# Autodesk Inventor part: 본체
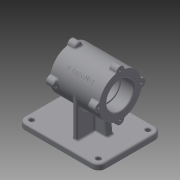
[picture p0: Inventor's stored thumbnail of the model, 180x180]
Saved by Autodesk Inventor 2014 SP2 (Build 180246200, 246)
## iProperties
Created: 2015-12
Part Number: 본체
Material: Generic
Document SubType Name: Modeling
Designer: Administrator
Density: 1 g/cm^3
Appearance: Default
Author: Administrator
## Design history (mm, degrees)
sketch "스케치1"
  geometry: L1 (-70, 55)-(70, 55); L2 (70, 55)-(70, -55); L3 (70, -55)-(-70, -55); L4 (-70, -55)-(-70, 55); 3 further points
  constraints: 8 end point, 2 midpoint, 2 parallel, 1 horizontal, 1 horizontal alignment, 1 perpendicular, 1 vertical alignment
  dimensions: "d0" = 140 distance of L1.start L1.end; "d1" = 110 distance of L3.end L1.start
extrude "돌출1" new body sketch "스케치1" distance "d2" = 10; taper "d3" = 0 deg
node "작업 평면2"
  node "작업 평면1"
sketch "스케치2"
  geometry: L1 (70, -9.931)-(70, -82.976); L2 (-10, -55)-(85.359, -55); C1 r 37 at (70, -55)
  constraints: 4 end point, 2 point on line, 1 centre point, 1 perpendicular, 1 vertical
  dimensions: "d5" = 80 distance from line of L2.start L1; "d6" = 74 diameter of C1
extrude "돌출2" join sketch "스케치2" stored distance "d7" = 85; taper "d8" = 0 deg
sketch "스케치3"
  geometry: L1 (70, -55)-(-10, -55); L2 (0, -110)-(0, 0) reference; L3 (70, -92)-(-6.296, -92); L4 (70, -18)-(-6.296, -18); L5 (70, -18)-(70, -92); L6 (-6.296, -92)-(-6.296, -18); A1 r 37 centre (70, -55) between (70, -92) and (70, -18) reference
  constraints: 10 end point, 2 perpendicular, 2 point on circle, 2 symmetric about line, 1 horizontal, 1 parallel, 1 point on line
  dimensions: "d10" = 37 distance between parallel lines of L1 L3
extrude "돌출3" join sketch "스케치3" stored distance "d11" = 8; taper "d12" = 0 deg
sketch "스케치4"
  geometry: L1 (35, 50.324)-(35, 4.64); L2 (6, 10)-(14, 10) reference; L3 (10, 10)-(10, 60.476); L4 (70, 10)-(-70, 10) reference; L5 (35, 10)-(30.049, 50.324); L6 (35, 10)-(75.627, 10); L7 (-15, 10)-(-10.049, 50.324); L8 (-10.049, 50.324)-(30.049, 50.324); L9 (35, 10)-(-15, 10); 1 further point
  constraints: 14 end point, 2 parallel, 2 point on line, 2 symmetric about line, 1 equal length, 1 horizontal, 1 midpoint, 1 perpendicular, 1 vertical
  dimensions: "d13" = 25 distance between parallel lines of L1 L3; "d14" = 97 deg angle of L6 L5
extrude "돌출4" join sketch "스케치4" stored distance "d15" = 12; taper "d16" = 0 deg
sketch "스케치5"
  geometry: C1 r 37 at (0, 0) reference; C2 r 23.5 at (0, 0); 1 further point
  constraints: 1 centre point, 1 coincident
  dimensions: "d17" = 47 diameter of C2
extrude "돌출5" cut sketch "스케치5" distance "d18" = 22; taper "d19" = 0 deg
sketch "스케치6"
  geometry: C1 r 23.5 at (0, 0) reference; C2 r 21 at (0, 0); 1 further point
  constraints: 1 centre point, 1 coincident
  dimensions: "d20" = 42 diameter of C2
extrude "돌출6" cut sketch "스케치6" distance "d21" = 41; taper "d22" = 0 deg
sketch "스케치7"
  geometry: C1 r 37 at (0, 0) reference; C2 r 23.5 at (0, 0); 1 further point
  constraints: 1 centre point, 1 coincident
  dimensions: "d23" = 47 diameter of C2
extrude "돌출7" cut sketch "스케치7" distance "d24" = 22; taper "d25" = 0 deg
node "작업 평면3"
sketch "스케치9"
  geometry: L1 (70, 55)-(-70, 55) reference; L2 (-70, 55)-(-70, -55) reference; L3 (6, -37)-(6, -6) reference; L4 (0, 0)-(0, 16.938); L5 (0, 0)-(-28.163, 0); C1 r 4 at (-58, 43); C2 r 4 at (58, 43); C3 r 4 at (-58, -43); C4 r 4 at (58, -43)
  constraints: 4 centre point, 4 end point, 3 symmetric about line, 1 parallel, 1 perpendicular, 3 other
  dimensions: "d32" = 8 diameter of C1; "d33" = 12 distance from line of L1 C1.centre; "d34" = 12 distance from line of L2 C1.centre
extrude "돌출9" cut sketch "스케치9" distance "d35" = 15; taper "d36" = 0 deg
node "작업 평면4"
sketch "스케치10"
  geometry: L1 (37, 70)-(10.837, 96.163); L2 (37, 70)-(74, 70); C1 r 21 at (37, 70) reference; 1 further point
  constraints: 4 end point, 1 equal length, 1 horizontal
  dimensions: "d37" = 37 distance of L1.start L1.end; "d38" = 135 deg angle of L2 L1
node "작업 평면5"
sketch "스케치11"
  geometry: L1 (25.377, -5.139)-(-25.377, -5.139); L2 (-25.377, -5.139)-(-25.377, 10.054); L3 (-25.377, 10.054)-(25.377, 10.054); L4 (25.377, 10.054)-(25.377, -5.139); L5 (0, -5.139)-(0, 10.054); L6 (42.5, -26.163)-(42.5, -26.163) reference; 1 further point
  constraints: 2 end point, 2 midpoint, 2 other
  dimensions: "d39" = 42.5 distance between parallel lines of L6 L5
feature "엠보싱1" sketch "스케치11" dims "d0" = 140, "d1" = 110, "d40" = 0.5, "d41" = 0
fillet "모깎기1" dims "d56" = 0.3, "d57" = 3, "d58" = 12
chamfer "모따기1" distance "d59" = 1; stored, may be unused: second distance "d60" = 2, angle "d61" = 45 deg
fillet "모깎기2" dims "d62" = 3
sketch "스케치14"
  geometry: L1 (-32.5, 117)-(52.5, 117) reference; L2 (-17.5, 115.281)-(-17.5, 117); L3 (-32.5, 117)-(-32.5, 117) reference; L4 (-17.5, 117)-(-20.048, 124); L5 (-17.5, 117)-(-1.549, 117); L6 (-32.5, 124)-(-20.048, 124); L7 (-32.5, 117)-(-32.5, 124); L8 (-17.5, 117)-(-32.5, 117); 1 further point
  constraints: 12 end point, 2 perpendicular, 1 horizontal, 1 parallel, 1 point on line
  dimensions: "d63" = 15 distance between parallel lines of L3 L2; "d64" = 110 deg angle of L5 L4; "d65" = 7 distance between parallel lines of L1 L6
revolve "회전1" sketch "스케치14" stored, may be unused: angle "d66" = 90 deg
node "작업 평면7"
  node "작업 평면6"
sketch "스케치15"
  geometry: A1 r 7 centre (55, 107) between (61.969, 106.338) and (48.031, 106.338) reference; A2 r 7 centre (18, 70) between (18.662, 76.969) and (18.662, 63.031) reference; A3 r 7 centre (55, 33) between (48.031, 33.662) and (61.969, 33.662) reference; A4 r 7 centre (92, 70) between (91.338, 63.031) and (91.338, 76.969) reference; 5 further points
  constraints: 4 coincident
hole "구멍3" sketch "스케치15" at (55, 107), (92, 70), (55, 33), (18, 70) diameter "d72" = 3.242; stored, may be unused: countersink angle "d76" = 90 deg, drill point angle "d78" = 118 deg; dims "d73" = 9, "d74" = 4, "d75" = 2, "d77" = 11
sketch "스케치16"
  geometry: A1 r 7 centre (-55, 33) between (-61.969, 33.662) and (-48.031, 33.662) reference; A2 r 7 centre (-18, 70) between (-18.662, 63.031) and (-18.662, 76.969) reference; A3 r 7 centre (-55, 107) between (-48.031, 106.338) and (-61.969, 106.338) reference; A4 r 7 centre (-92, 70) between (-91.338, 76.969) and (-91.338, 63.031) reference; 5 further points
  constraints: 4 coincident
hole "구멍4" sketch "스케치16" at (-55, 107), (-18, 70), (-55, 33), (-92, 70) diameter "d79" = 3.242; stored, may be unused: countersink angle "d83" = 90 deg, drill point angle "d85" = 118 deg; dims "d80" = 9, "d81" = 4, "d82" = 2, "d84" = 11
fillet "모깎기3" dims "d86" = 3
node "솔리드1"
pattern_circular "원형 패턴1" dims angle "d68" = 360 deg
mirror "대칭2"
